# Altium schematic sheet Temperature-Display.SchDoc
size A4; SheetNumber: 1; SheetTotal: 1
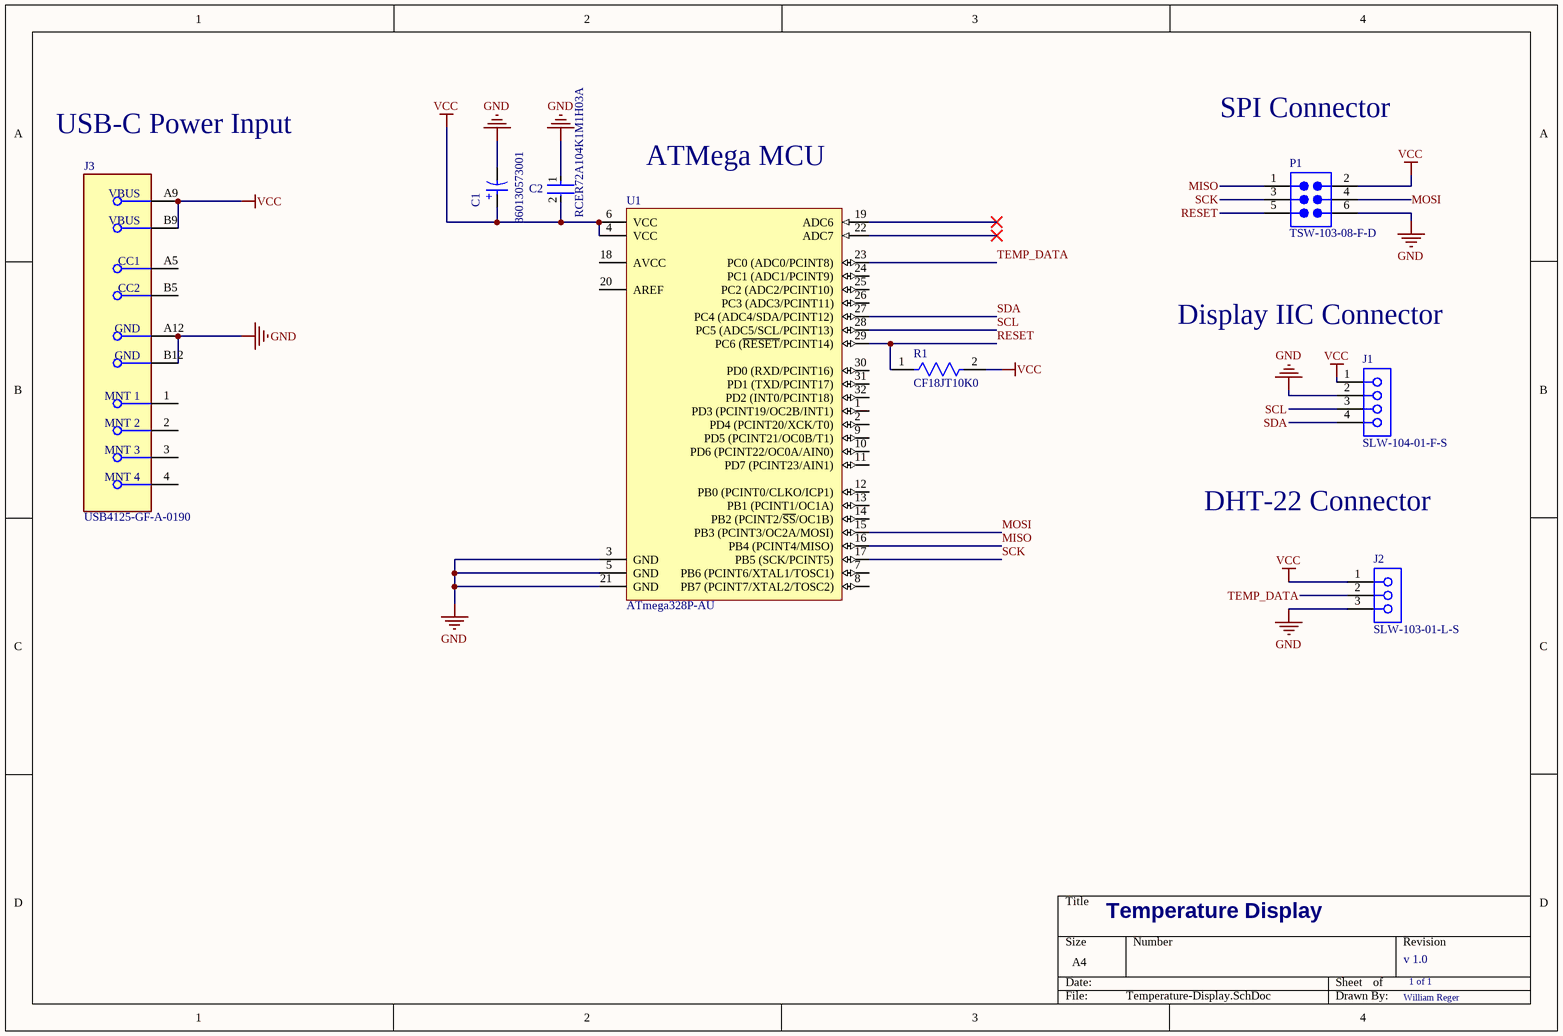
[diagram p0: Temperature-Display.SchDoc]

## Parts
C1  860130573001  [WCAP-ATET_D6.3H11]
C2  RCER72A104K1M1H03A  [FP-RCE1K1-2_5-MFG]
J1  SLW-104-01-F-S  [SMTC-SLW-104-01-X-S]
J2  SLW-103-01-L-S  [SMTC-SLW-103-01-X-S]
J3  USB4125-GF-A-0190  [FP-USB4125-GF-A-0190-MFG]
P1  TSW-103-08-F-D  [SMTC-TSW-103-08-X-D]
R1  CF18JT10K0  [FP-CF18-MFG]
U1  ATmega328P-AU  [32A_M]

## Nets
GND: C1.2(N) C2.1 J1.2 J2.3 J3.A12(GND) J3.B12(GND) P1.6 U1.3(GND) U1.5(GND) U1.21(GND)
VCC: C1.1(P) C2.2 J1.1 J2.1 J3.A9(VBUS) J3.B9(VBUS) P1.2 R1.2 U1.4(VCC) U1.6(VCC)
MISO: P1.1 U1.16(PB4_(PCINT4/MISO))
MOSI: P1.4 U1.15(PB3_(PCINT3/OC2A/MOSI))
RESET: P1.5 R1.1 U1.29(PC6_(~{RESET}/PCINT14))
SCK: P1.3 U1.17(PB5_(SCK/PCINT5))
SCL: J1.3 U1.28(PC5_(ADC5/SCL/PCINT13))
SDA: J1.4 U1.27(PC4_(ADC4/SDA/PCINT12))
TEMP_DATA: J2.2 U1.23(PC0_(ADC0/PCINT8))

Not connected (* = marked no-connect by the designer): J3 1(MNT_1) 2(MNT_2) 3(MNT_3) 4(MNT_4) A5(CC1) B5(CC2); U1 1(PD3_(PCINT19/OC2B/INT1)) 2(PD4_(PCINT20/XCK/T0)) 7(PB6_(PCINT6/XTAL1/TOSC1)) 8(PB7_(PCINT7/XTAL2/TOSC2)) 9(PD5_(PCINT21/OC0B/T1)) 10(PD6_(PCINT22/OC0A/AIN0)) 11(PD7_(PCINT23/AIN1)) 12(PB0_(PCINT0/CLKO/ICP1)) 13(PB1_(PCINT1/OC1A)) 14(PB2_(PCINT2/~{SS}/OC1B)) 18(AVCC) 19(ADC6)* 20(AREF) 22(ADC7)* 24(PC1_(ADC1/PCINT9)) 25(PC2_(ADC2/PCINT10)) 26(PC3_(ADC3/PCINT11)) 30(PD0_(RXD/PCINT16)) 31(PD1_(TXD/PCINT17)) 32(PD2_(INT0/PCINT18))

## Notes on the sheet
- USB-C Power Input
- (near U1) ATMega MCU
- SPI Connector
- (near J1) Display IIC Connector
- DHT-22 Connector
- Temperature Display
- v 1.0
- 1 of 1
- William Reger

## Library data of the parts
C1 = CMP-03913-54218083-2: WCAP-ATET Aluminum Electrolytic Capacitors; Ripple Current: 82mA; Life (Hours): 1000hours; Leakage Current: 7.7µA; Capacitance: 22µF; Voltage Rating (DC): 35V; Polarity: Polar; Pitch: 2.5mm; Tolerance: 20%; Value: 22µF
C2 = CMP-06035-028865-1: Cap Ceramic Monolithic 100nF 100V 10% Thru-Hole Bulk; Dielectric: X7R; Lead Diameter: 0.5mm; Lead/Base Style: Formed Leads
J1 = CMP-1023-00132-1: Low Profile Socket Strips, Through-hole, Vertical, -55 to 125 degC, 2.54 mm Pitch, 4-Pin, Female, RoHS; Manufacturer: Samtec; Pitch: 2.54 mm
J2 = CMP-1023-00127-1: Low Profile Socket Strips, Through-hole, Vertical, -55 to 125 degC, 2.54 mm Pitch, 3-Pin, Female, RoHS; Manufacturer: Samtec; Pitch: 2.54 mm
J3 = CMP-245163-000004-1: CONN RCPT TYPE C 6P SMD RA
P1 = CMP-1024-00337-1: 0.025" SQ Post Header, Through-hole, Vertical, -55 to 125 degC, 2.54 mm Pitch, 6-Pin, Male, RoHS; Manufacturer: Samtec; Pitch: 2.54 mm
R1 = CMP-26528-000002-1: RES 10K OHM 1/8W 5% CF AXIAL; Manufacturer: Stackpole Electronics; Power Rating: 0.125W; Temperature Coefficient: 0-500ppm/°C; Resistance: 10kΩ; Voltage Rating: 250V; Value: 10kΩ
U1 = CMP-0095-00269-2: 8-bit AVR Microcontroller, 32KB Flash, 1KB EEPROM, 2KB SRAM, 32-pin TQFP, Industrial Grade (-40°C to 85°C)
